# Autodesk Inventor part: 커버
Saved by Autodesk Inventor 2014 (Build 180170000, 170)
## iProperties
Created: 2026-04
Part Number: 커버
Material: 일반
Document SubType Name: Modeling
Designer: dg
Density: 1 g/cm^3
Appearance: 기본값
Author: dg
Author: jhkim
Creation Date: 2026-03-26
Sending System: Autodesk Inventor 2026
Preprocessor: ST-DEVELOPER v20.1
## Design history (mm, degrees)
node "커버1"
node "솔리드1"
node "기준1"
